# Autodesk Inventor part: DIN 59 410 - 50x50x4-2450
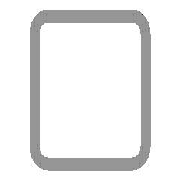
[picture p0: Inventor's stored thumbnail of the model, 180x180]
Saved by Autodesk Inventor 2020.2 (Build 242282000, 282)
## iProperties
Manager: www.cadconsulting.pl
Company: Fabian Stasiak CAD Consulting
Created: 2014-02
Part Number: DIN 59 410 - 50x50x4-2450
Material: Stal, miękka
Description: Rurki stalowe o przekroju kwadratowym formowane na gorąco
Document SubType Name: Modellieren
Standard: DIN
Designer: F.Stasiak
Standards Organization: DIN
Language: pl-PL
Size Designation: 50x50x4
Categories: <MemberInstance><Categories><Category DisplayName="Kształtowniki konstrukcyjne" InternalName="089c4875-fa83-4c05-b084-43b9cc11f5ed" Mnemonic="GRDR"><CategoryPar
Stock Number: 50x50x4
Density: 7.85 g/cm^3
Appearance: Częściowo polerowana
Mass: 13362.7 g
Surface Area: 8525.15 cm^2
Volume: 1702.25 cm^3
Catalog Web Link: www.expertbooks.pl
_CCFamilyMember: 40
_CCFamilyDisplayName: DIN 59410 (Kwadrat) - Rurki stalowe o przekroju kwadratowym formowane na gorąco
_FrameMemberDoc: Frame Member File
_Version: 15.0.0
_GetPNFromCC: 1
G_W: 50,000 mm
G_H: 50,000 mm
+97981DE3-4444-4721-9E96-2235860056B1+CUTDETAIL1: Wytnij
+D344F97D-B9A8-4A8F-AB2B-2488F5F87578+CUTDETAIL2: Wytnij
G_L: 2450,000 mm
IsCustomPart: 1
Author: F.Stasiak
Subject: Zbiór ćwiczeń. Autodesk Inventor 2020. Kurs Professional
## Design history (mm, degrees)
node "Płaszczyzna początkowa"
node "Płaszczyzna końcowa"
sketch "Szkic"
  geometry: L1 (-17, 25)-(17, 25); L2 (25, 17)-(25, -17); L3 (17, -25)-(-17, -25); L4 (-25, -17)-(-25, 17); L5 (-37.32, 0)-(37.32, 0) reference; L6 (0, -37.32)-(0, 37.32) reference; L7 (-17, 21)-(17, 21); L8 (21, 17)-(21, -17); L9 (17, -21)-(-17, -21); L10 (-21, -17)-(-21, 17); A1 r 8 centre (-17, 17) between (-17, 25) and (-25, 17); A2 r 8 centre (17, 17) between (25, 17) and (17, 25); A3 r 8 centre (17, -17) between (17, -25) and (25, -17); A4 r 8 centre (-17, -17) between (-25, -17) and (-17, -25); A5 r 4 centre (-17, 17) between (-17, 21) and (-21, 17); A6 r 4 centre (17, 17) between (21, 17) and (17, 21); A7 r 4 centre (17, -17) between (17, -21) and (21, -17); A8 r 4 centre (-17, -17) between (-21, -17) and (-17, -21); 3 further points
  constraints: 16 end point, 16 point on circle, 8 centre point, 8 tangent, 6 point on line, 4 parallel, 3 equal radius, 3 perpendicular, 1 horizontal, 7 other
  dimensions: "b" = 50 distance of point (-25, 25) point (25, 25); "msp_r" = 8 radius of A1 (= 2 x ParT); "d8" = 25 distance between parallel lines of L4 L6 (= d9); "d9" = 25 distance between parallel lines of L3 L5 (= 0.5 x b); "d10" = 4 distance between parallel lines of L3 L9 (= ParT)
extrude "Bryła" new body sketch "Szkic" taper "d4" = 0 deg; stored distance "NLG" = 10
node "Driven Length"
  sketch "Sketch2"
    geometry: L1 (0, 0)-(10, 0) reference
    constraints: 2 end point, 1 horizontal
  workplane "Work Plane3"
  sketch "Sketch3"
    geometry: L1 (-2, 25)-(12, 25) reference; L2 (-2, 2475)-(12, 2475) reference
    dimensions: "d14" = 2450 distance between parallel lines of L1 L2 (derived)
node "Płaszczyzna konstrukcyjna4"
feature "Podział1"
node "Płaszczyzna konstrukcyjna5"
feature "Podział2"
body "Solid1"
other parameters: "ParT" = 4, "G_OFFSET_START" = -25 [user parameter; used in 1 equation term], "G_OFFSET_END" = -25 [user parameter; used in 1 equation term], "d11" = 25 (= -G_OFFSET_START), "d12" = 2475 (= G_OFFSET_END + B_L), "G_L" = 2450 (= d14) [user parameter], "d13" = 90 deg
